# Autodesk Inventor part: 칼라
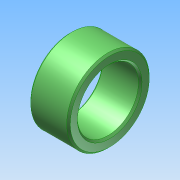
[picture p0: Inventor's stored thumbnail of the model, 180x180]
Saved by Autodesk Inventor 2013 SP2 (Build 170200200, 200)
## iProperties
Created: 2025-05
Part Number: 칼라
Material: Generic
Document SubType Name: Modeling
Designer: a
Density: 1 g/cm^3
Author: a
변환 표준: STEP AP214IS
전처리기: Build: 200, Release: 2013 SP2 Update 6 - Date: Thu 07/17/2014
전송 단위: 밀리미터
불확실성: 0.01
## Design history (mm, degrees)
node "칼라1"
node "솔리드1"
node "기준1"
